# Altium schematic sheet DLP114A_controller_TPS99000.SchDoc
size 558 x 431 mm; Date: Not shown in title block; ApprovedBy: Not shown in title block; CheckedBy: Not shown in title block; Author: Not shown in title block; CompanyName: Not shown in title block; Engineer: Not shown in title block; Organization: Not shown in title block; Address1: Not shown in title block; Address2: Not shown in title block; Address3: Not shown in title block; Address4: Not shown in title block; DocumentNumber: 3; Revision: Use project parameter SCH_Rev; SheetNumber: 3; SheetTotal: 7; PageSetup: Record=PageOptions¦CenterHorizontal=True¦CenterVertical=True¦PrintScale=0.69¦XCorrection=1.00¦YCorrection=1.00¦PrintKind=0¦BorderSize=5000000¦LeftOffset=0¦BottomOffset=0¦Orientation=2¦PaperLength=1000¦PaperWidth=1000¦Scale=100¦PaperSource=15¦PrintQuality=600¦MediaType=1¦DitherType=10¦PaperKind=Letter¦PrintScaleMode=1
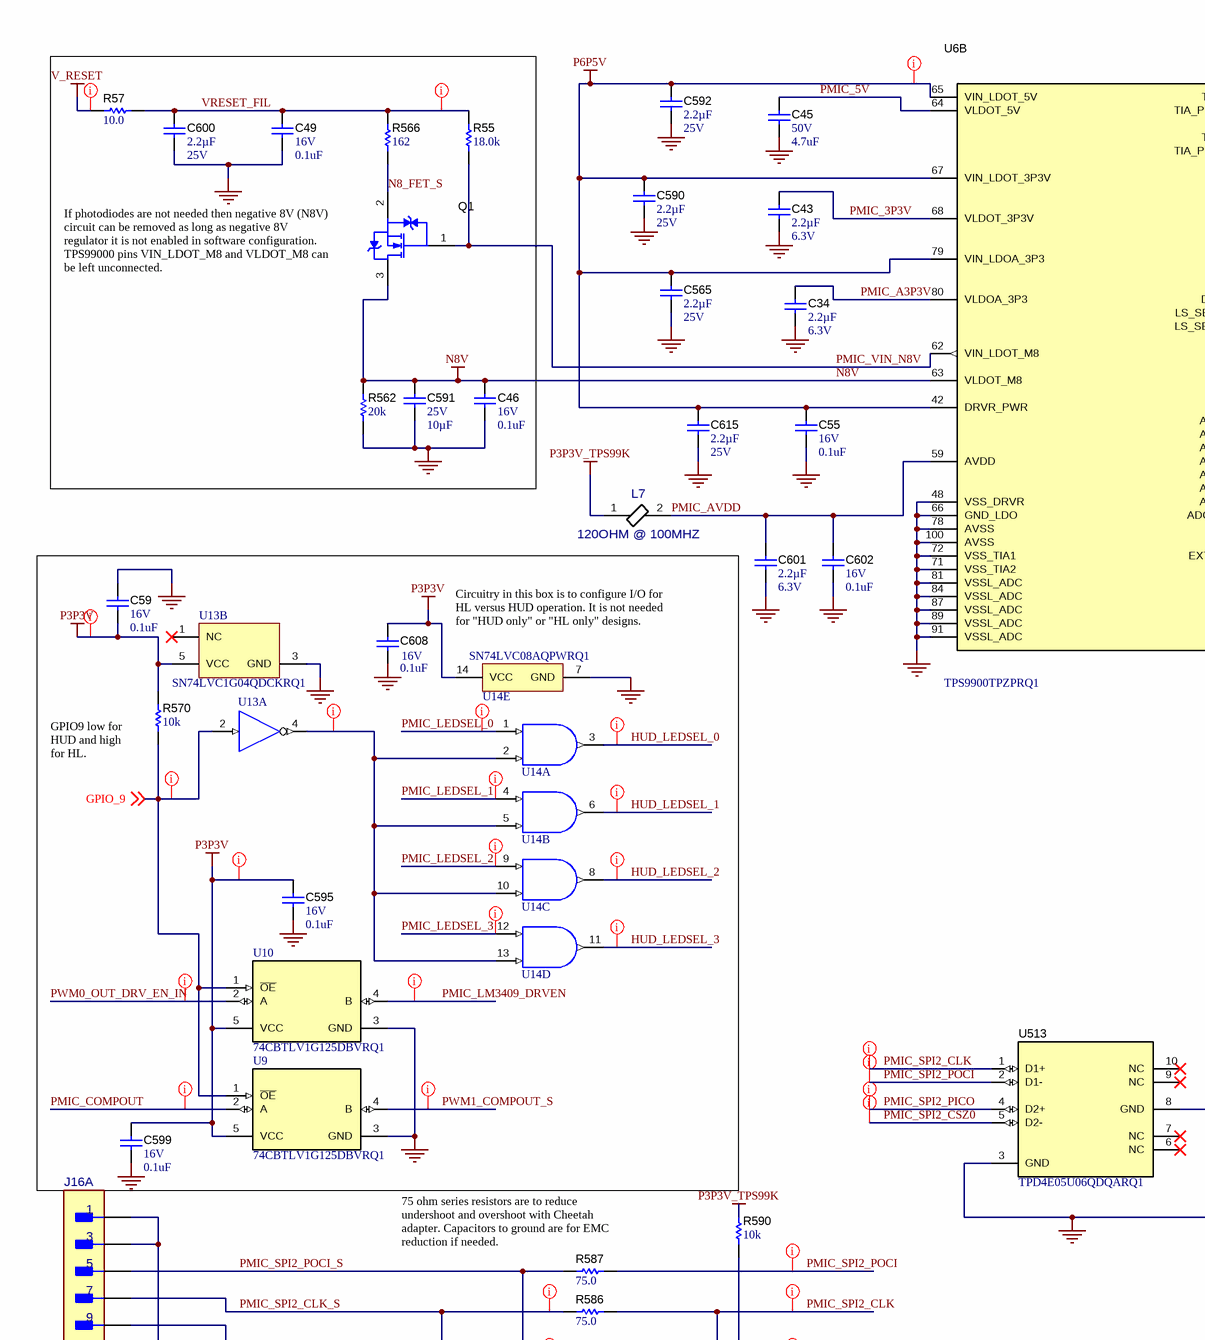
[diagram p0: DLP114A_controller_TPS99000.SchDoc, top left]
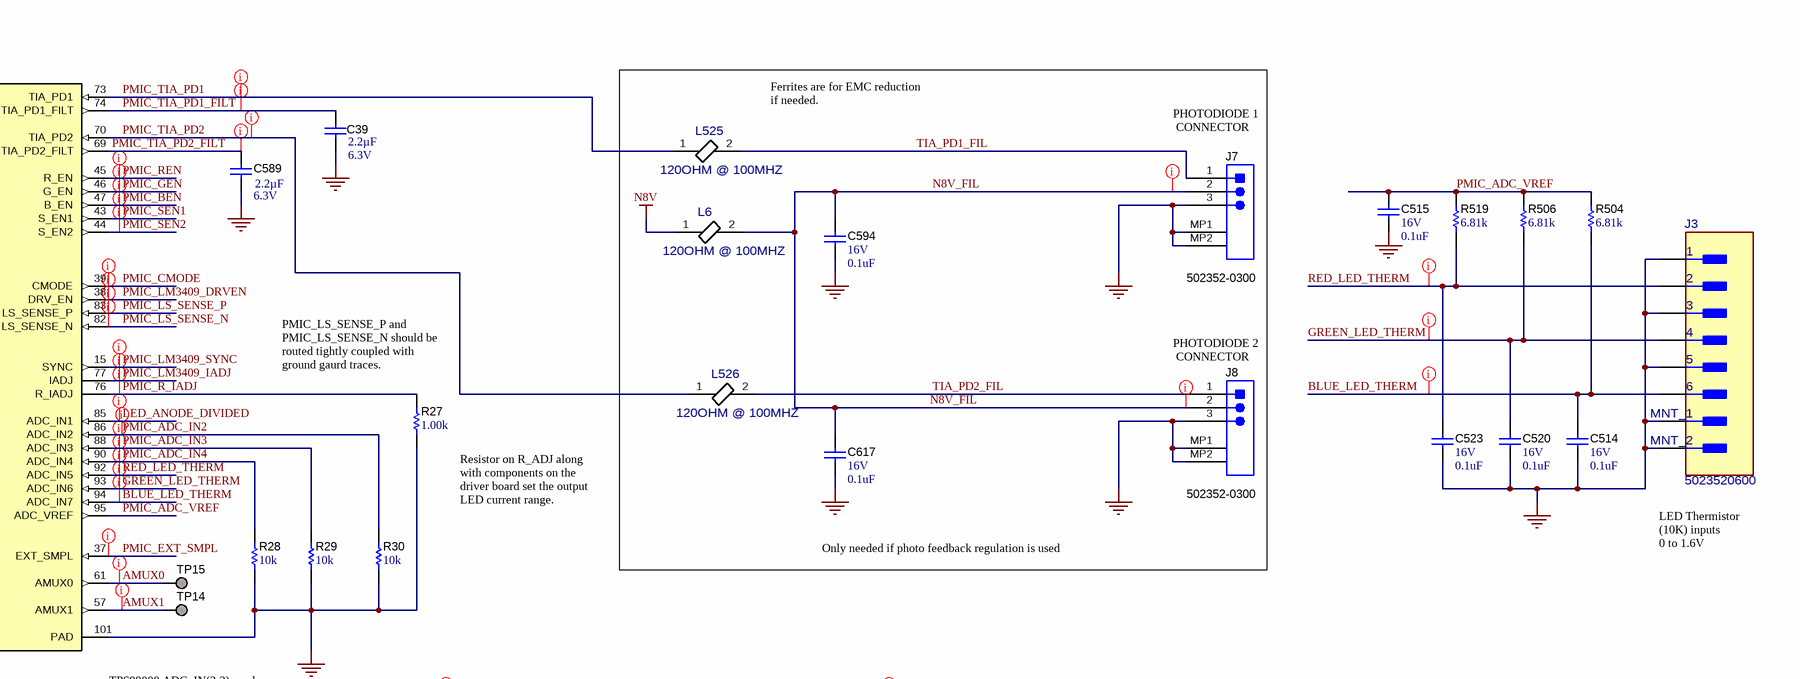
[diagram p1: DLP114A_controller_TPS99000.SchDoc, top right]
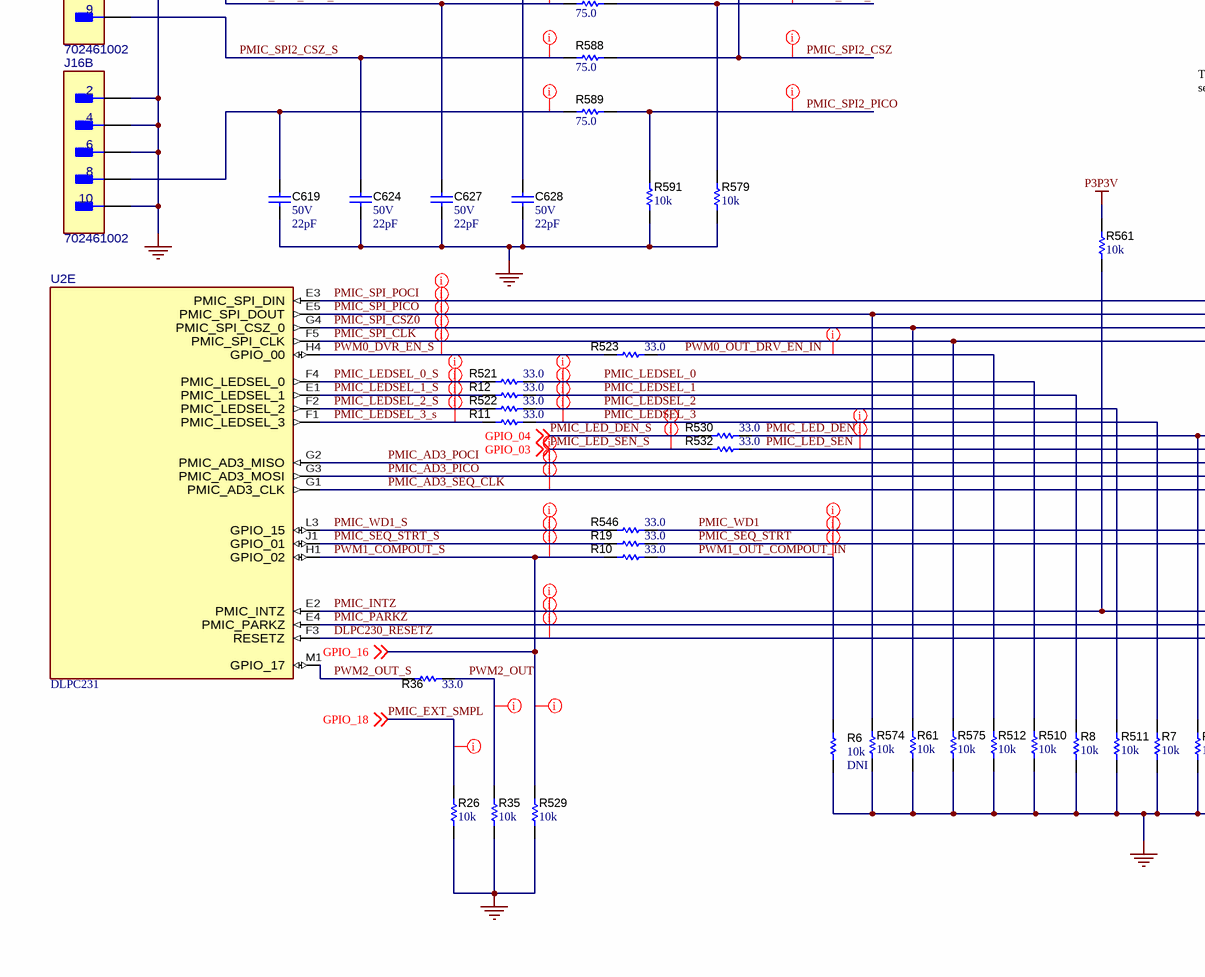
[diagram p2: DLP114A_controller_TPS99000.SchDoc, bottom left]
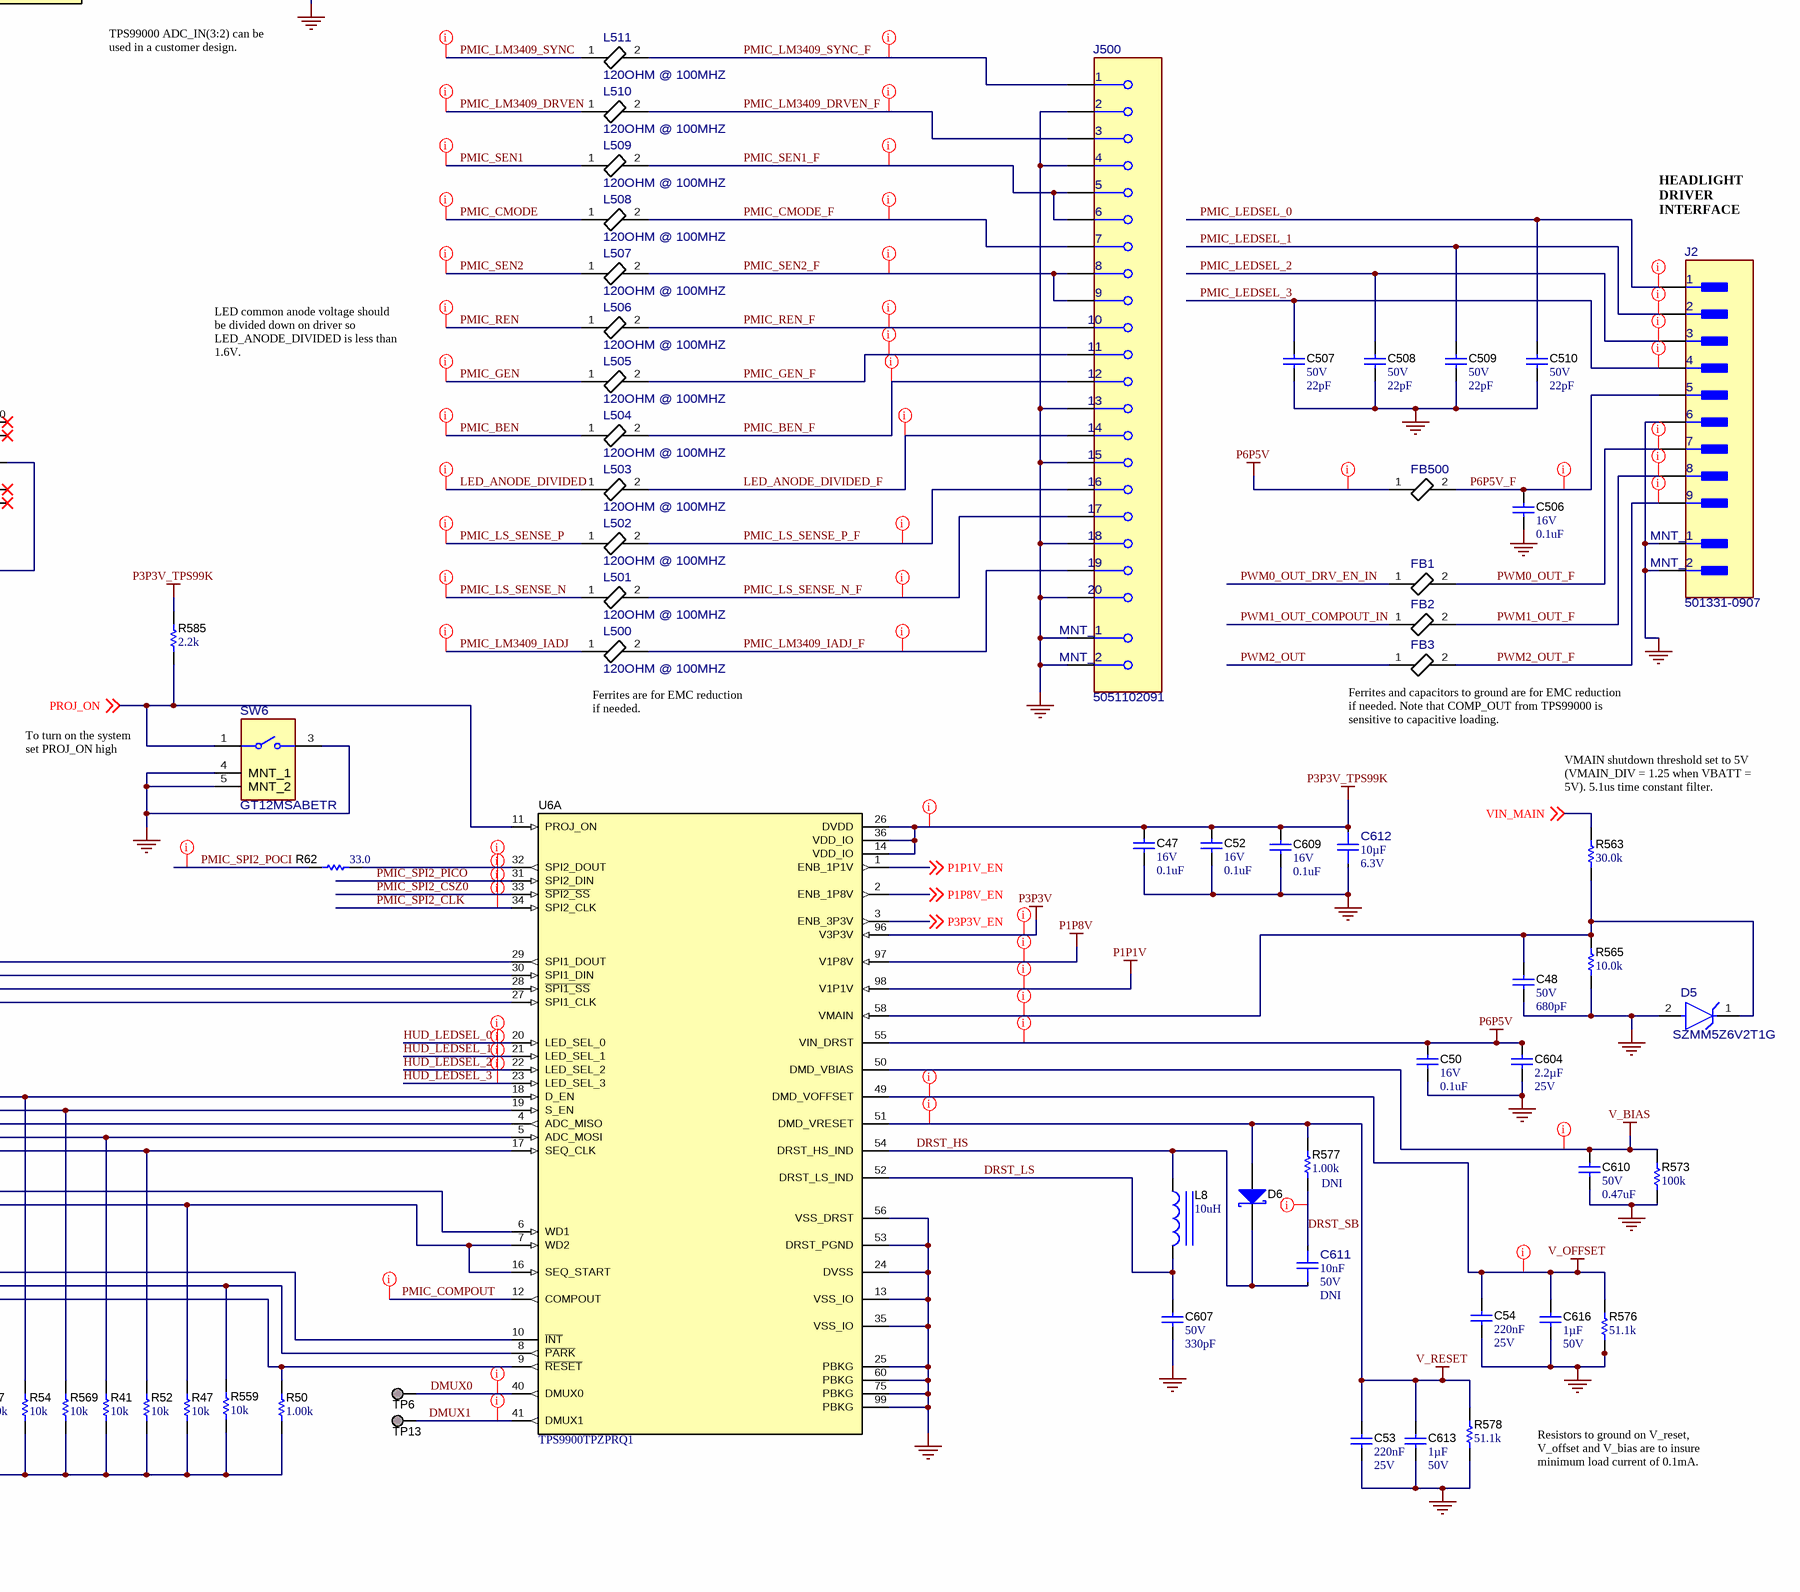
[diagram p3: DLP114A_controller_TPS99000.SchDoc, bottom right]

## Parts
C34  Cap_F: 2.2µF  VDC_V: 6.3V  [0603]  (hidden comment: GCM188R70J225KE22D)
C39  Cap_F: 2.2µF  VDC_V: 6.3V  [0603]  (hidden comment: GCM188R70J225KE22D)
C43  Cap_F: 2.2µF  VDC_V: 6.3V  [0603]  (hidden comment: GCM188R70J225KE22D)
C45  VDC_V: 50V  ValueDisplayed: 4.7uF  [1210_280]  (hidden comment: CGA6P3X7R1H475M250AB)
C46  VDC_V: 16V  ValueDisplayed: 0.1uF  [0402]  (hidden comment: GCM155R71C104KA55D)
C47  VDC_V: 16V  ValueDisplayed: 0.1uF  [0402]  (hidden comment: GCM155R71C104KA55D)
C48  VDC_V: 50V  ValueDisplayed: 680pF  [0402]  (hidden comment: GCM1555C1H681FA16D)
C49  VDC_V: 16V  ValueDisplayed: 0.1uF  [0402]  (hidden comment: GCM155R71C104KA55D)
C50  VDC_V: 16V  ValueDisplayed: 0.1uF  [0402]  (hidden comment: GCM155R71C104KA55D)
C52  VDC_V: 16V  ValueDisplayed: 0.1uF  [0402]  (hidden comment: GCM155R71C104KA55D)
C53  Cap_F: 220nF  VDC_V: 25V  [0603]  (hidden comment: GCM188R71E224KA55D)
C54  Cap_F: 220nF  VDC_V: 25V  [0603]  (hidden comment: GCM188R71E224KA55D)
C55  VDC_V: 16V  ValueDisplayed: 0.1uF  [0402]  (hidden comment: GCM155R71C104KA55D)
C59  VDC_V: 16V  ValueDisplayed: 0.1uF  [0402]  (hidden comment: GCM155R71C104KA55D)
C506  VDC_V: 16V  ValueDisplayed: 0.1uF  [0402]  (hidden comment: GCM155R71C104KA55D)
C507  VDC_V: 50V  ValueDisplayed: 22pF  [0402]  (hidden comment: CL05C220JB5NNNC)
C508  VDC_V: 50V  ValueDisplayed: 22pF  [0402]  (hidden comment: CL05C220JB5NNNC)
C509  VDC_V: 50V  ValueDisplayed: 22pF  [0402]  (hidden comment: CL05C220JB5NNNC)
C510  VDC_V: 50V  ValueDisplayed: 22pF  [0402]  (hidden comment: CL05C220JB5NNNC)
C514  VDC_V: 16V  ValueDisplayed: 0.1uF  [0402]  (hidden comment: GCM155R71C104KA55D)
C515  VDC_V: 16V  ValueDisplayed: 0.1uF  [0402]  (hidden comment: GCM155R71C104KA55D)
C520  VDC_V: 16V  ValueDisplayed: 0.1uF  [0402]  (hidden comment: GCM155R71C104KA55D)
C523  VDC_V: 16V  ValueDisplayed: 0.1uF  [0402]  (hidden comment: GCM155R71C104KA55D)
C565  Cap_F: 2.2µF  VDC_V: 25V  [0805_HV]  (hidden comment: CGA4J3X7R1E225K125AB)
C589  Cap_F: 2.2µF  VDC_V: 6.3V  [0603]  (hidden comment: GCM188R70J225KE22D)
C590  Cap_F: 2.2µF  VDC_V: 25V  [0805_HV]  (hidden comment: CGA4J3X7R1E225K125AB)
C591  VDC_V: 25V  ValueDisplayed: 10µF  [1206_180]  (hidden comment: C1206C106J3RACAUTO)
C592  Cap_F: 2.2µF  VDC_V: 25V  [0805_HV]  (hidden comment: CGA4J3X7R1E225K125AB)
C594  VDC_V: 16V  ValueDisplayed: 0.1uF  [0402]  (hidden comment: GCM155R71C104KA55D)
C595  VDC_V: 16V  ValueDisplayed: 0.1uF  [0402]  (hidden comment: GCM155R71C104KA55D)
C599  VDC_V: 16V  ValueDisplayed: 0.1uF  [0402]  (hidden comment: GCM155R71C104KA55D)
C600  Cap_F: 2.2µF  VDC_V: 25V  [0805_HV]  (hidden comment: CGA4J3X7R1E225K125AB)
C601  Cap_F: 2.2µF  VDC_V: 6.3V  [0603]  (hidden comment: GCM188R70J225KE22D)
C602  VDC_V: 16V  ValueDisplayed: 0.1uF  [0402]  (hidden comment: GCM155R71C104KA55D)
C604  Cap_F: 2.2µF  VDC_V: 25V  [0805_HV]  (hidden comment: CGA4J3X7R1E225K125AB)
C607  VDC_V: 50V  ValueDisplayed: 330pF  [0402]  (hidden comment: CGA2B2X7R1H331K050BA)
C608  VDC_V: 16V  ValueDisplayed: 0.1uF  [0402]  (hidden comment: GCM155R71C104KA55D)
C609  VDC_V: 16V  ValueDisplayed: 0.1uF  [0402]  (hidden comment: GCM155R71C104KA55D)
C610  VDC_V: 50V  ValueDisplayed: 0.47uF  [1206_180]  (hidden comment: CGA5L2X7R1H474K160AA)
C611  ValueDisplayed: 10nF  VDC_V: 50V  Parameter 1: DNI  [FP-GCM155R71H103KA55D_0402-MFG]  (hidden comment: GCM155R71H103KA55D)
C612  Cap_F: 10µF  VDC_V: 6.3V  [FP-CGA4J1X7R0J106K125AC_0805-MFG]  (hidden comment: CGA4J1X7R0J106K125AC)
C613  Cap_F: 1µF  VDC_V: 50V  [0805_HV]  (hidden comment: 08055C105K4Z2A)
C615  Cap_F: 2.2µF  VDC_V: 25V  [0805_HV]  (hidden comment: CGA4J3X7R1E225K125AB)
C616  Cap_F: 1µF  VDC_V: 50V  [0805_HV]  (hidden comment: 08055C105K4Z2A)
C617  VDC_V: 16V  ValueDisplayed: 0.1uF  [0402]  (hidden comment: GCM155R71C104KA55D)
C619  VDC_V: 50V  ValueDisplayed: 22pF  [0402]  (hidden comment: CL05C220JB5NNNC)
C624  VDC_V: 50V  ValueDisplayed: 22pF  [0402]  (hidden comment: CL05C220JB5NNNC)
C627  VDC_V: 50V  ValueDisplayed: 22pF  [0402]  (hidden comment: CL05C220JB5NNNC)
C628  VDC_V: 50V  ValueDisplayed: 22pF  [0402]  (hidden comment: CL05C220JB5NNNC)
D5  SZMM5Z6V2T1G  [FP-SZMM5Z6V2T1G_SOD523-MFG]
D6  MBR0540T1G  [SOD-123]  (value not drawn)
FB1  MMZ1005Y121CTD25  [FP-MMZ1005Y121CTD25_0402-MFG]  (value not drawn)
FB2  MMZ1005Y121CTD25  [FP-MMZ1005Y121CTD25_0402-MFG]  (value not drawn)
FB3  MMZ1005Y121CTD25  [FP-MMZ1005Y121CTD25_0402-MFG]  (value not drawn)
FB500  MMZ1005Y121CTD25  [FP-MMZ1005Y121CTD25_0402-MFG]  (value not drawn)
J2  501331-0907  [FP-501331-0907_HDR9-MFG]
J3  5023520600  [FP-5023520600_HDR6-MFG]
J7  502352-0300  [Molex_502352-0300]
J8  502352-0300  [Molex_502352-0300]
J16  702461002  [FP-702461002_HDR10-MFG]  (parts A,B of 2)
J500  5051102091  [FP-5051102091_CONN_FFC_FPC20-MFG]
L6  120OHM @ 100MHZ  [FP-MMZ1005Y121CTD25_0402-MFG]
L7  120OHM @ 100MHZ  [FP-MMZ1005Y121CTD25_0402-MFG]
L8  ValueDisplayed: 10uH  [CDRH5D18]  (hidden comment: CDRH5D18NP-100NC)
L500  120OHM @ 100MHZ  [FP-MMZ1005Y121CTD25_0402-MFG]
L501  120OHM @ 100MHZ  [FP-MMZ1005Y121CTD25_0402-MFG]
L502  120OHM @ 100MHZ  [FP-MMZ1005Y121CTD25_0402-MFG]
L503  120OHM @ 100MHZ  [FP-MMZ1005Y121CTD25_0402-MFG]
L504  120OHM @ 100MHZ  [FP-MMZ1005Y121CTD25_0402-MFG]
L505  120OHM @ 100MHZ  [FP-MMZ1005Y121CTD25_0402-MFG]
L506  120OHM @ 100MHZ  [FP-MMZ1005Y121CTD25_0402-MFG]
L507  120OHM @ 100MHZ  [FP-MMZ1005Y121CTD25_0402-MFG]
L508  120OHM @ 100MHZ  [FP-MMZ1005Y121CTD25_0402-MFG]
L509  120OHM @ 100MHZ  [FP-MMZ1005Y121CTD25_0402-MFG]
L510  120OHM @ 100MHZ  [FP-MMZ1005Y121CTD25_0402-MFG]
L511  120OHM @ 100MHZ  [FP-MMZ1005Y121CTD25_0402-MFG]
L525  120OHM @ 100MHZ  [FP-MMZ1005Y121CTD25_0402-MFG]
L526  120OHM @ 100MHZ  [FP-MMZ1005Y121CTD25_0402-MFG]
Q1  NX3008NBKW,115  [SOT-323]  (value not drawn)
R6  ValueDisplayed: 10k  Parameter 1: DNI  [0402]  (hidden comment: ERJ-2GEJ103X)
R7  ValueDisplayed: 10k  [0402]  (hidden comment: ERJ-2GEJ103X)
R8  ValueDisplayed: 10k  [0402]  (hidden comment: ERJ-2GEJ103X)
R10  ValueDisplayed: 33.0  [0402]  (hidden comment: ERJ-2RKF33R0X)
R11  ValueDisplayed: 33.0  [0402]  (hidden comment: ERJ-2RKF33R0X)
R12  ValueDisplayed: 33.0  [0402]  (hidden comment: ERJ-2RKF33R0X)
R19  ValueDisplayed: 33.0  [0402]  (hidden comment: ERJ-2RKF33R0X)
R26  ValueDisplayed: 10k  [0402]  (hidden comment: ERJ-2GEJ103X)
R27  ValueDisplayed: 1.00k  [0402]  (hidden comment: CRCW04021K00FKED)
R28  ValueDisplayed: 10k  [0402]  (hidden comment: ERJ-2GEJ103X)
R29  ValueDisplayed: 10k  [0402]  (hidden comment: ERJ-2GEJ103X)
R30  ValueDisplayed: 10k  [0402]  (hidden comment: ERJ-2GEJ103X)
R35  ValueDisplayed: 10k  [0402]  (hidden comment: ERJ-2GEJ103X)
R36  ValueDisplayed: 33.0  [0402]  (hidden comment: ERJ-2RKF33R0X)
R41  ValueDisplayed: 10k  [0402]  (hidden comment: ERJ-2GEJ103X)
R47  ValueDisplayed: 10k  [0402]  (hidden comment: ERJ-2GEJ103X)
R50  ValueDisplayed: 1.00k  [0402]  (hidden comment: CRCW04021K00FKED)
R52  ValueDisplayed: 10k  [0402]  (hidden comment: ERJ-2GEJ103X)
R54  ValueDisplayed: 10k  [0402]  (hidden comment: ERJ-2GEJ103X)
R55  ValueDisplayed: 18.0k  [0402]  (hidden comment: ERJ2RKF1802X)
R57  ValueDisplayed: 10.0  [0402]  (hidden comment: CRCW040210R0FKED)
R61  ValueDisplayed: 10k  [0402]  (hidden comment: ERJ-2GEJ103X)
R62  ValueDisplayed: 33.0  [0402]  (hidden comment: ERJ-2RKF33R0X)
R504  ValueDisplayed: 6.81k  [0402]  (hidden comment: CRCW04026K81FKED)
R506  ValueDisplayed: 6.81k  [0402]  (hidden comment: CRCW04026K81FKED)
R510  ValueDisplayed: 10k  [0402]  (hidden comment: ERJ-2GEJ103X)
R511  ValueDisplayed: 10k  [0402]  (hidden comment: ERJ-2GEJ103X)
R512  ValueDisplayed: 10k  [0402]  (hidden comment: ERJ-2GEJ103X)
R519  ValueDisplayed: 6.81k  [0402]  (hidden comment: CRCW04026K81FKED)
R521  ValueDisplayed: 33.0  [0402]  (hidden comment: ERJ-2RKF33R0X)
R522  ValueDisplayed: 33.0  [0402]  (hidden comment: ERJ-2RKF33R0X)
R523  ValueDisplayed: 33.0  [0402]  (hidden comment: ERJ-2RKF33R0X)
R529  ValueDisplayed: 10k  [0402]  (hidden comment: ERJ-2GEJ103X)
R530  ValueDisplayed: 33.0  [0402]  (hidden comment: ERJ-2RKF33R0X)
R532  ValueDisplayed: 33.0  [0402]  (hidden comment: ERJ-2RKF33R0X)
R546  ValueDisplayed: 33.0  [0402]  (hidden comment: ERJ-2RKF33R0X)
R559  ValueDisplayed: 10k  [0402]  (hidden comment: ERJ-2GEJ103X)
R561  ValueDisplayed: 10k  [0402]  (hidden comment: ERJ-2GEJ103X)
R562  ValueDisplayed: 20k  [0402]  (hidden comment: ERJ-2GEJ203X)
R563  ValueDisplayed: 30.0k  [0402]  (hidden comment: CRCW040230K0FKED)
R565  ValueDisplayed: 10.0k  [0402]  (hidden comment: ERJ-2RKF1002X)
R566  ValueDisplayed: 162  [0402]  (hidden comment: CRCW0402162RFKED)
R569  ValueDisplayed: 10k  [0402]  (hidden comment: ERJ-2GEJ103X)
R570  ValueDisplayed: 10k  [0402]  (hidden comment: ERJ-2GEJ103X)
R573  ValueDisplayed: 100k  [0402]  (hidden comment: ERJ-2GEJ104X)
R574  ValueDisplayed: 10k  [0402]  (hidden comment: ERJ-2GEJ103X)
R575  ValueDisplayed: 10k  [0402]  (hidden comment: ERJ-2GEJ103X)
R576  ValueDisplayed: 51.1k  [0402]  (hidden comment: CRCW040251K1FKED)
R577  ValueDisplayed: 1.00k  Parameter 1: DNI  [0402]  (hidden comment: CRCW04021K00FKED)
R578  ValueDisplayed: 51.1k  [0402]  (hidden comment: CRCW040251K1FKED)
R579  ValueDisplayed: 10k  [0402]  (hidden comment: ERJ-2GEJ103X)
R585  ValueDisplayed: 2.2k  [0402]  (hidden comment: CRCW04022K20JNED)
R586  ValueDisplayed: 75.0  [0402]  (hidden comment: CRCW040275R0FKED)
R587  ValueDisplayed: 75.0  [0402]  (hidden comment: CRCW040275R0FKED)
R588  ValueDisplayed: 75.0  [0402]  (hidden comment: CRCW040275R0FKED)
R589  ValueDisplayed: 75.0  [0402]  (hidden comment: CRCW040275R0FKED)
R590  ValueDisplayed: 10k  [0402]  (hidden comment: ERJ-2GEJ103X)
R591  ValueDisplayed: 10k  [0402]  (hidden comment: ERJ-2GEJ103X)
SW6  GT12MSABETR  [FP-GT12MSABETR_SMT_7MM01_6MM93-MFG]
TP6  TESTPOINT  [TESTPOINT]  (value not drawn)  (no BOM)
TP13  TESTPOINT  [TESTPOINT]  (value not drawn)  (no BOM)
TP14  TESTPOINT  [TESTPOINT]  (value not drawn)  (no BOM)
TP15  TESTPOINT  [TESTPOINT]  (value not drawn)  (no BOM)
U2  DLPC231  [ZEK0324A-MFG]  (part E of 9)
U6  TPS9900TPZPRQ1  [PZP0100K]  (parts A,B of 2)
U9  74CBTLV1G125DBVRQ1  [DBV0005A_N]
U10  74CBTLV1G125DBVRQ1  [DBV0005A_N]
U13  SN74LVC1G04QDCKRQ1  [DCK0005A_N]  (value not drawn)  (parts A,B of 2)
U14  SN74LVC08AQPWRQ1  [PW0014A_N]  (parts A,B,C,D,E of 5)
U513  TPD4E05U06QDQARQ1  [DQA0010A]

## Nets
GND: C34.2 C39.2 C43.2 C45.2 C46.2 C47.2 C48.2 C49.2 C50.2 C52.2 C53.2 C54.2 C55.2 C59.2 C506.2 C507.2 C508.2 C509.2 C510.2 C514.2 C515.2 C520.2 C523.2 C565.2 C589.2 C590.2 C591.2 C592.2 C594.2 C595.2 C599.2 C600.2 C601.2 C602.2 C604.2 C607.2 C608.2 C609.2 C610.2 C612.1 C613.2 C615.2 C616.2 C617.2 C619.2 C624.2 C627.2 C628.2 D5.2(ANODE) J2.6 J2.10(MNT_1) J2.11(MNT_2) J3.1 J3.3 J3.5 J3.7(MNT_1) J3.8(MNT_2) J7.3 J7.MP1 J7.MP2 J8.3 J8.MP1 J8.MP2 J16.1 J16.2 J16.3 J16.4 J16.6 J16.10 J500.2 J500.4 J500.13 J500.15 J500.18 J500.20 J500.21(MNT_1) J500.22(MNT_2) R6.1 R7.1 R8.1 R26.1 R27.1 R28.1 R29.1 R30.1 R35.1 R41.1 R47.1 R50.1 R52.1 R54.1 R61.1 R510.1 R511.1 R512.1 R529.1 R559.1 R562.1 R565.1 R569.1 R573.1 R574.1 R575.1 R576.1 R578.1 R579.1 R591.1 SW6.3 SW6.4(MNT_1) SW6.5(MNT_2) U6.13(VSS_IO) U6.24(DVSS) U6.25(PBKG) U6.35(VSS_IO) U6.48(VSS_DRVR) U6.53(DRST_PGND) U6.56(VSS_DRST) U6.60(PBKG) U6.66(GND_LDO) U6.71(VSS_TIA2) U6.72(VSS_TIA1) U6.75(PBKG) U6.78(AVSS) U6.81(VSSL_ADC) U6.84(VSSL_ADC) U6.87(VSSL_ADC) U6.89(VSSL_ADC) U6.91(VSSL_ADC) U6.99(PBKG) U6.100(AVSS) U6.101(PAD) U9.3(GND) U10.3(GND) U13.3(GND) U14.7(GND) U513.3(GND) U513.8(GND)
N8V: C46.1 C591.1 L6.1 Q1.3(D) R562.2 U6.63(VLDOT_M8)
P1P1V: U6.98(V1P1V)
P1P8V: U6.97(V1P8V)
P3P3V: C59.1 C595.1 C599.1 C608.1 R561.2 R570.2 U6.96(V3P3V) U9.5(VCC) U10.5(VCC) U13.5(VCC) U14.14(VCC)
P3P3V_TPS99K: C47.1 C52.1 C609.1 C612.2 L7.1 R585.2 R590.2 U6.14(VDD_IO) U6.26(DVDD) U6.36(VDD_IO)
P6P5V: C50.1 C55.1 C565.1 C590.1 C592.1 C604.1 C615.1 FB500.1 U6.42(DRVR_PWR) U6.55(VIN_DRST) U6.65(VIN_LDOT_5V) U6.67(VIN_LDOT_3P3V) U6.79(VIN_LDOA_3P3)
V_BIAS: C610.1 R573.2 U6.50(DMD_VBIAS)
V_OFFSET: C54.1 C616.1 R576.2 U6.49(DMD_VOFFSET)
V_RESET: C53.1 C613.1 D6.2(A) R57.1 R577.2 R578.2 U6.51(DMD_VRESET)
AMUX0: TP15.1 U6.61(AMUX0)
AMUX1: TP14.1 U6.57(AMUX1)
BLUE_LED_THERM: C514.1 J3.6 R504.1 U6.94(ADC_IN7)
DLPC230_RESETZ: R50.2 U2.F3(RESETZ) U6.9(~{RESET})
DMUX0: TP6.1 U6.40(DMUX0)
DMUX1: TP13.1 U6.41(DMUX1)
DRST_HS: C611.1 D6.1(K) L8.1 U6.54(DRST_HS_IND)
DRST_LS: C607.1 L8.2 U6.52(DRST_LS_IND)
DRST_SB: C611.2 R577.1
GPIO_9: R570.1 U9.1(~{OE}) U10.1(~{OE}) U13.2(A) ; off-sheet GPIO_9
GREEN_LED_THERM: C520.1 J3.4 R506.1 U6.93(ADC_IN6)
HUD_LEDSEL_0: U6.20(LED_SEL_0) U14.3(1Y)
HUD_LEDSEL_1: U6.21(LED_SEL_1) U14.6(2Y)
HUD_LEDSEL_2: U6.22(LED_SEL_2) U14.8(3Y)
HUD_LEDSEL_3: U6.23(LED_SEL_3) U14.11(4Y)
LED_ANODE_DIVIDED: L503.1 U6.85(ADC_IN1)
LED_ANODE_DIVIDED_F: J500.14 L503.2
N8_FET_S: Q1.2(S) R566.1
N8V_FIL: C594.1 C617.1 J7.2 J8.2 L6.2
P1P1V_EN: U6.1(ENB_1P1V) ; off-sheet P1P1V_EN
P1P8V_EN: U6.2(ENB_1P8V) ; off-sheet P1P8V_EN
P3P3V_EN: U6.3(ENB_3P3V) ; off-sheet P3P3V_EN
P6P5V_F: C506.1 FB500.2 J2.5
PMIC_3P3V: C43.1 U6.68(VLDOT_3P3V)
PMIC_5V: C45.1 U6.64(VLDOT_5V)
PMIC_A3P3V: C34.1 U6.80(VLDOA_3P3)
PMIC_AD3_PICO: R41.2 U2.G3(PMIC_AD3_MOSI) U6.5(ADC_MOSI)
PMIC_AD3_POCI: U2.G2(PMIC_AD3_MISO) U6.4(ADC_MISO)
PMIC_AD3_SEQ_CLK: R52.2 U2.G1(PMIC_AD3_CLK) U6.17(SEQ_CLK)
PMIC_ADC_IN2: R30.2 U6.86(ADC_IN2)
PMIC_ADC_IN3: R29.2 U6.88(ADC_IN3)
PMIC_ADC_IN4: R28.2 U6.90(ADC_IN4)
PMIC_ADC_VREF: C515.1 R504.2 R506.2 R519.2 U6.95(ADC_VREF)
PMIC_AVDD: C601.1 C602.1 L7.2 U6.59(AVDD)
PMIC_BEN: L504.1 U6.47(B_EN)
PMIC_BEN_F: J500.12 L504.2
PMIC_CMODE: L508.1 U6.39(CMODE)
PMIC_CMODE_F: J500.7 L508.2
PMIC_COMPOUT: U6.12(COMPOUT) U9.2(A)
PMIC_EXT_SMPL: R26.2 U6.37(EXT_SMPL) ; off-sheet GPIO_18  [also labelled GPIO_18]
PMIC_GEN: L505.1 U6.46(G_EN)
PMIC_GEN_F: J500.11 L505.2
PMIC_INTZ: R561.1 U2.E2(PMIC_INTZ) U6.10(~{INT})
PMIC_LED_DEN: R54.2 R530.2 U6.18(D_EN)
PMIC_LED_DEN_S: R530.1 ; off-sheet GPIO_04  [also labelled GPIO_04]
PMIC_LED_SEN: R532.2 R569.2 U6.19(S_EN)
PMIC_LED_SEN_S: R532.1 ; off-sheet GPIO_03  [also labelled GPIO_03]
PMIC_LEDSEL_0: C510.1 J2.1 R510.2 R521.2 U14.1(1A)
PMIC_LEDSEL_0_S: R521.1 U2.F4(PMIC_LEDSEL_0)
PMIC_LEDSEL_1: C509.1 J2.2 R8.2 R12.2 U14.4(2A)
PMIC_LEDSEL_1_S: R12.1 U2.E1(PMIC_LEDSEL_1)
PMIC_LEDSEL_2: C508.1 J2.3 R511.2 R522.2 U14.9(3A)
PMIC_LEDSEL_2_S: R522.1 U2.F2(PMIC_LEDSEL_2)
PMIC_LEDSEL_3: C507.1 J2.4 R7.2 R11.2 U14.12(4A)
PMIC_LEDSEL_3_s: R11.1 U2.F1(PMIC_LEDSEL_3)
PMIC_LM3409_DRVEN: L510.1 U6.38(DRV_EN) U10.4(B)
PMIC_LM3409_DRVEN_F: J500.3 L510.2
PMIC_LM3409_IADJ: L500.1 U6.77(IADJ)
PMIC_LM3409_IADJ_F: J500.19 L500.2
PMIC_LM3409_SYNC: L511.1 U6.15(SYNC)
PMIC_LM3409_SYNC_F: J500.1 L511.2
PMIC_LS_SENSE_N: L501.1 U6.82(LS_SENSE_N)
PMIC_LS_SENSE_N_F: J500.17 L501.2
PMIC_LS_SENSE_P: L502.1 U6.83(LS_SENSE_P)
PMIC_LS_SENSE_P_F: J500.16 L502.2
PMIC_PARKZ: R559.2 U2.E4(PMIC_PARKZ) U6.8(~{PARK})
PMIC_R_IADJ: R27.2 U6.76(R_IADJ)
PMIC_REN: L506.1 U6.45(R_EN)
PMIC_REN_F: J500.10 L506.2
PMIC_SEN1: L509.1 U6.43(S_EN1)
PMIC_SEN1_F: J500.5 J500.6 L509.2
PMIC_SEN2: L507.1 U6.44(S_EN2)
PMIC_SEN2_F: J500.8 J500.9 L507.2
PMIC_SEQ_STRT: R19.2 R47.2 U6.7(WD2) U6.16(SEQ_START)
PMIC_SEQ_STRT_S: R19.1 U2.J1(GPIO_01)
PMIC_SPI2_CLK: R579.2 R586.2 U6.34(SPI2_CLK) U513.1(D1+)
PMIC_SPI2_CLK_S: C627.1 J16.7 R586.1
PMIC_SPI2_CSZ: R588.2 R590.1
PMIC_SPI2_CSZ0: U6.33(~{SPI2_SS}) U513.5(D2-)
PMIC_SPI2_CSZ_S: C624.1 J16.9 R588.1
PMIC_SPI2_PICO: R589.2 R591.2 U6.31(SPI2_DIN) U513.4(D2+)
PMIC_SPI2_POCI: R62.1 R587.2 U513.2(D1-)
PMIC_SPI2_POCI_S: C628.1 J16.5 R587.1
PMIC_SPI_CLK: R575.2 U2.F5(PMIC_SPI_CLK) U6.27(SPI1_CLK)
PMIC_SPI_CSZ0: R61.2 U2.G4(PMIC_SPI_CSZ_0) U6.28(~{SPI1_SS})
PMIC_SPI_PICO: R574.2 U2.E5(PMIC_SPI_DOUT) U6.30(SPI1_DIN)
PMIC_SPI_POCI: U2.E3(PMIC_SPI_DIN) U6.29(SPI1_DOUT)
PMIC_TIA_PD1: L525.1 U6.73(TIA_PD1)
PMIC_TIA_PD1_FILT: C39.1 U6.74(TIA_PD1_FILT)
PMIC_TIA_PD2: L526.1 U6.70(TIA_PD2)
PMIC_TIA_PD2_FILT: C589.1 U6.69(TIA_PD2_FILT)
PMIC_VIN_N8V: Q1.1(G) R55.1 U6.62(VIN_LDOT_M8)
PMIC_WD1: R546.2 U6.6(WD1)
PMIC_WD1_S: R546.1 U2.L3(GPIO_15)
PROJ_ON: R585.1 SW6.1 U6.11(PROJ_ON) ; off-sheet PROJ_ON
PWM0_DVR_EN_S: R523.1 U2.H4(GPIO_00)
PWM0_OUT_DRV_EN_IN: FB1.1 R512.2 R523.2 U10.2(A)
PWM0_OUT_F: FB1.2 J2.7
PWM1_COMPOUT_S: R10.1 R529.2 U2.H1(GPIO_02) U9.4(B) ; off-sheet GPIO_16  [also labelled GPIO_16]
PWM1_OUT_COMPOUT_IN: FB2.1 R6.2 R10.2
PWM1_OUT_F: FB2.2 J2.8
PWM2_OUT: FB3.1 R35.2 R36.2
PWM2_OUT_F: FB3.2 J2.9
PWM2_OUT_S: R36.1 U2.M1(GPIO_17)
RED_LED_THERM: C523.1 J3.2 R519.1 U6.92(ADC_IN5)
TIA_PD1_FIL: J7.1 L525.2
TIA_PD2_FIL: J8.1 L526.2
VIN_MAIN: R563.2 ; off-sheet VIN_MAIN
VRESET_FIL: C49.1 C600.1 R55.2 R57.2 R566.2
NetC48_1: C48.1 D5.1(CATHODE) R563.1 R565.2 U6.58(VMAIN)
NetC619_1: C619.1 J16.8 R589.1
NetR62_2: R62.2 U6.32(SPI2_DOUT)
NetU13_4: U13.4(Y) U14.2(1B) U14.5(2B) U14.10(3B) U14.13(4B)

Not connected (* = marked no-connect by the designer): U13 1(NC)*; U513 6(NC)* 7(NC)* 9(NC)* 10(NC)*

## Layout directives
net class 50OHM: AMUX0, AMUX1, BLUE_LED_THERM, DLPC230_RESETZ, DMUX0, DMUX1, DRST_SB, GPIO_9, GREEN_LED_THERM, HUD_LEDSEL_0, HUD_LEDSEL_1, HUD_LEDSEL_2, HUD_LEDSEL_3, LED_ANODE_DIVIDED, LED_ANODE_DIVIDED_F, N8V_FIL, NetC619_1, NetR62_2, NetU13_4, PMIC_AD3_PICO, PMIC_AD3_POCI, PMIC_AD3_SEQ_CLK, PMIC_ADC_IN2, PMIC_ADC_IN3, PMIC_ADC_IN4, PMIC_BEN, PMIC_BEN_F, PMIC_CMODE, PMIC_CMODE_F, PMIC_COMPOUT, PMIC_EXT_SMPL, PMIC_GEN, PMIC_GEN_F, PMIC_INTZ, PMIC_LED_DEN, PMIC_LED_DEN_S, PMIC_LED_SEN, PMIC_LED_SEN_S, PMIC_LEDSEL_0, PMIC_LEDSEL_0_S, PMIC_LEDSEL_1, PMIC_LEDSEL_1_S, PMIC_LEDSEL_2, PMIC_LEDSEL_2_S, PMIC_LEDSEL_3, PMIC_LEDSEL_3_s, PMIC_LM3409_DRVEN, PMIC_LM3409_DRVEN_F, PMIC_LM3409_IADJ, PMIC_LM3409_IADJ_F, PMIC_LM3409_SYNC, PMIC_LM3409_SYNC_F, PMIC_LS_SENSE_N, PMIC_LS_SENSE_N_F, PMIC_LS_SENSE_P, PMIC_LS_SENSE_P_F, PMIC_PARKZ, PMIC_R_IADJ, PMIC_REN, PMIC_REN_F, PMIC_SEN1, PMIC_SEN1_F, PMIC_SEN2, PMIC_SEN2_F, PMIC_SEQ_STRT, PMIC_SEQ_STRT_S, PMIC_SPI2_CLK, PMIC_SPI2_CLK_S, PMIC_SPI2_CSZ, PMIC_SPI2_CSZ0, PMIC_SPI2_CSZ_S, PMIC_SPI2_PICO, PMIC_SPI2_POCI, PMIC_SPI_CLK, PMIC_SPI_CSZ0, PMIC_SPI_PICO, PMIC_SPI_POCI, PMIC_TIA_PD1, PMIC_TIA_PD1_FILT, PMIC_TIA_PD2, PMIC_TIA_PD2_FILT, PMIC_WD1, PMIC_WD1_S, PWM0_DVR_EN_S, PWM0_OUT_DRV_EN_IN, PWM0_OUT_F, PWM1_COMPOUT_S, PWM1_OUT_COMPOUT_IN, PWM1_OUT_F, PWM2_OUT, PWM2_OUT_F, RED_LED_THERM, VRESET_FIL
net class POWER: NetC48_1, P1P1V, P1P8V, P3P3V, P3P3V_TPS99K, P6P5V, P6P5V_F
net class Voltage Spacing (15Mils): V_BIAS, V_OFFSET, V_RESET

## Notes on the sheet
- Ferrites are for EMC reduction
  if needed.
- (near J7) PHOTODIODE 1
  CONNECTOR
- (near Q1) If photodiodes are not needed then negative 8V (N8V)
  circuit can be removed as long as negative 8V
  regulator it is not enabled in software configuration.
  TPS99000 pins VIN_LDOT_M8 and VLDOT_M8 can
  be left unconnected.
- (near R27) PMIC_LS_SENSE_P and
  PMIC_LS_SENSE_N should be
  routed tightly coupled with
  ground gaurd traces.
- (near J8) PHOTODIODE 2
  CONNECTOR
- (near R27) Resistor on R_ADJ along
  with components on the
  driver board set the output
  LED current range.
- Only needed if photo feedback regulation is used
- LED Thermistor
  (10K) inputs
  0 to 1.6V
- (near U14) Circuitry in this box is to configure I/O for HL versus HUD operation. It is not needed for "HUD only" or "HL only" designs.
- TPS99000 ADC_IN(3:2) can be
  used in a customer design.
- (near R570) GPIO9 low for HUD and high for HL.
- HEADLIGHT
  DRIVER
  INTERFACE
- LED common anode voltage should
  be divided down on driver so
  LED_ANODE_DIVIDED is less than
  1.6V.
- (near R587) 75 ohm series resistors are to reduce
  undershoot and overshoot with Cheetah
  adapter. Capacitors to ground are for EMC
  reduction if needed.
- (near L500) Ferrites are for EMC reduction
  if needed.
- (near FB3) Ferrites and capacitors to ground are for EMC reduction
  if needed. Note that COMP_OUT from TPS99000 is
  sensitive to capacitive loading.
- To turn on the system
  set PROJ_ON high
- (near R563) VMAIN shutdown threshold set to 5V
  (VMAIN_DIV = 1.25 when VBATT =
  5V). 5.1us time constant filter.
- Resistors to ground on V_reset,
  V_offset and V_bias are to insure
  minimum load current of 0.1mA.

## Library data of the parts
C34 C39 C43 C589 C601 = CMP-0007134-5: CAP, CERM, 2.2 uF, 6.3 V, +/- 10%, X7R, AEC-Q200 Grade 1, 0603; Manufacturer: MuRata; TaMin_C: -55°C; Polarized: N; SizeAreaWB_mm2: 4.68; Value1: Unknown; U/M: EA; Value: 2.2uF; TaMax_C: 125°C; SizeZ_mm: 1; SizeX_mm: 1.6; SizeY_mm: 0.8; SizeArea_mm2: 1.28; AEC Qualified: Y; AEC Category: Q200
C45 = CMP-0009163-2: CAP, CERM, 4.7 uF, 50 V, +/- 20%, X7R, AEC-Q200 Grade 1, 1210; Manufacturer: TDK; TaMin_C: -55°C; Polarized: N; SizeAreaWB_mm2: 14.7; Value1: Unknown; U/M: EA; Value: 4.7uF; TaMax_C: 125°C; SizeZ_mm: 2.8; SizeX_mm: 3.2; SizeY_mm: 2.5; Cap_Case: 1210; SizeArea_mm2: 8; AEC Qualified: Y; Cap_F: 4.7µF; AEC Grade: 1; AEC Category: Q200
C46 C47 C49 C50 C52 C55 C59 C506 C514 C515 C520 C523 C594 C595 C599 C602 C608 C609 C617 = CMP-0006351-2: CAP, CERM, 0.1 uF, 16 V, +/- 10%, X7R, 0402; Manufacturer: MuRata; TaMin_C: -55°C; Polarized: N; SizeAreaWB_mm2: 3; Value1: Unknown; U/M: EA; Value: 0.1uF; TaMax_C: 125°C; SizeZ_mm: 0.6; SizeX_mm: 1; SizeY_mm: 0.5; Cap_F: 100nF; AEC Category: Q200
C48 = CMP-0086096-1: CAP, CERM, 680 pF, 50 V,+/- 1%, C0G/NP0, AEC-Q200 Grade 1, 0402; Manufacturer: MuRata; SizeArea_mm2: 0.5; Polarized: N; SizeZ_mm: 0.6; SizeAreaWB_mm2: 3; AEC Qualified: Y; Value: 680pF; TaMin_C: -55°C; SizeX_mm: 1; U/M: EA; TaMax_C: 125°C; AEC Category: Q200
C53 C54 = CMP-0007140-4: CAP, CERM, 0.22 uF, 25 V, +/- 10%, X7R, AEC-Q200 Grade 1, 0603; Manufacturer: MuRata; TaMin_C: -55°C; Polarized: N; SizeAreaWB_mm2: 4.68; Value1: Unknown; U/M: EA; Value: 0.22uF; TaMax_C: 125°C; SizeZ_mm: 1; SizeX_mm: 1.6; SizeY_mm: 0.8; SizeArea_mm2: 1.28; AEC Qualified: Y; AEC Category: Q200
C507-C510 C619 C624 C627 C628 = CMP-0085851-1: CAP, CERM, 22 pF, 50 V,+/- 5%, C0G/NP0, 0402; Manufacturer: Walsin; AEC Qualified: N; TaMax_C: 125°C; SizeX_mm: 1; Value: 22pF; SizeZ_mm: 0.6; AEC Category: Q200; TaMin_C: -55°C; SizeArea_mm2: 0.5; SizeAreaWB_mm2: 3; U/M: EA
C565 C590 C592 C600 C604 C615 = CMP-0007975-2: CAP, CERM, 2.2 uF, 25 V, +/- 10%, X7R, AEC-Q200 Grade 1, 0805; Manufacturer: TDK; TaMin_C: -55°C; Polarized: N; SizeAreaWB_mm2: 6.75; Value1: Unknown; U/M: EA; Value: 2.2uF; TaMax_C: 125°C; SizeZ_mm: 1.45; SizeX_mm: 2; SizeY_mm: 1.25; Cap_Case: 0805; SizeArea_mm2: 2.5; AEC Qualified: Y; AEC Grade: 1; AEC Category: Q200
C591 = CMP-0081062-1: CAP, CERM, 10 µF, 25 V,+/- 5%, X7R, AEC-Q200 Grade 1, 1206; Manufacturer: Kemet; TaMin_C: -55°C; Polarized: N; SizeAreaWB_mm2: 10.92; U/M: EA; Value: 10uF; TaMax_C: 125°C; SizeZ_mm: 1.8; SizeX_mm: 3.2; SizeY_mm: 1.6; SizeArea_mm2: 5.12; AEC Qualified: Y; AEC Grade: 1; AEC Category: Q200
C607 = CMP-0006318-2: CAP, CERM, 330 pF, 50 V, +/- 10%, X7R, AEC-Q200 Grade 1, 0402; Manufacturer: TDK; TaMin_C: -55°C; ESR_ohm: 6.5328; Polarized: N; SizeAreaWB_mm2: 3; Value1: 6.53276 ohm; U/M: EA; Value: 330pF; TaMax_C: 125°C; SizeZ_mm: 0.6; SizeX_mm: 1; SizeY_mm: 0.5; AEC Qualified: Y; IRMS_A: 212.649mA; AEC Category: Q200
C610 = CMP-0008776-2: CAP, CERM, 0.47 uF, 50 V, +/- 10%, X7R, AEC-Q200 Grade 1, 1206; Manufacturer: TDK; TaMin_C: -55°C; ESR_ohm: 9.426m; Polarized: N; SizeAreaWB_mm2: 10.92; Value1: 0.009426 ohm; U/M: EA; Value: 0.47uF; TaMax_C: 125°C; SizeZ_mm: 1.8; SizeX_mm: 3.2; SizeY_mm: 1.6; SizeArea_mm2: 5.12; AEC Qualified: Y; Cap_F: 470nF; IRMS_A: 2.37046A; AEC Grade: 1; AEC Category: Q200
C611 = CMP-0093287-1: Ceramic Capacitor for Automotive 10nF ±10% 50VDC X7R 0402 Paper T/R; Manufacturer: Murata; AEC Qualified: Yes; Tolerance_%: 0.1%; SizeZ_mm: 0.55mm; TempCo: 15%; AEC Grade: Grade 1
C612 = CMP-0093813-1: Cap Ceramic 10uF 6.3V X7R 10% Pad SMD 0805 +125°C Automotive T/R; Manufacturer: TDK Corporation; Value: 10µF; TempCo: 15%; AEC Qualified: Yes; AEC Grade: Grade 1; Tolerance_%: 0.1%; SizeZ_mm: 1.45mm
C613 C616 = CMP-0083705-1: CAP, CERM, 1 µF, 50 V,+/- 10%, X7R, AEC-Q200 Grade 1, 0805; Manufacturer: AVX; SizeAreaWB_mm2: 6.75; SizeArea_mm2: 2.5; AEC Qualified: Y; AEC Category: Q200; Value: 1uF; TaMax_C: 125°C; SizeZ_mm: 1.45; AEC Grade: 1; Polarized: N; TaMin_C: -55°C; SizeY_mm: 1.25; U/M: EA; SizeX_mm: 2; Cap_Case: 0805
D5 = CMP-0095722-1: Zener Diode 6.2 V 500 mW ±6.5% Surface Mount SOD-523; Manufacturer: onsemi; SizeZ_mm: 0.7mm; Vz_V: 6.2V; AEC Qualified: No; Vf_V: 6.6V; TJmax_C: 150°C; Vr_V: 4V; Zener Impedance: 10Ω; Power_W: 500mW; Max Reverse Leakage Current: 3uA
D6 = CMP-0028526-2: Diode, Schottky, 40 V, 0.5 A, SOD-123; Manufacturer: ON Semiconductor; Green_REACh: Passed; SizeY_mm: 1.7; Io_A: 500mA; SizeArea_mm2: 6.545; RJC_CperW: 118; Green_Lifecycle: Active; Vr_V: 40V; Vf_V: 510mV; TJmax_C: 150°C; AEC Category: Q101; SizeAreaWB_mm2: 13.095; Value1: 0.5A; SizeZ_mm: 1.35; SizeX_mm: 3.85; Value2: 0.51V; Value: 40V
FB1-FB3 FB500 = CMP-0086567-1: FERRITE BEAD 120 OHM 0402 1LN; Manufacturer: TDK; Imax_A: 0.4A; DCR_ohm: 0.18Ω; SizeZ_mm: 0.55mm; Symbol Name: SYM-MMZ1005Y121CTD25
J2 = CMP-0096269-1: Connector Header Surface Mount 9 position 0.039" (1.00mm); Manufacturer: Molex; Current_A: 1A; ContactFinish: Tin,Nickel; Row_Count: 1; AEC Qualified: No; Conn Orientation: Vertical; DUT-Pitch_mm: 1mm; Voltage_V: 100V; SizeZ_mm: 5.61mm; Conn Gender: Male
J3 = CMP-0086751-1: CONN HEADER SMD R/A 6POS 2MM; Manufacturer: Molex; Voltage_V: 125V; ContactFinish: Tin,Nickel; Row_Count: 1; Current_A: 3A
J7 J8 = CMP-0055291-1: Header(shrouded), 2mm, 3x1, Tin, R/A, SMT; Manufacturer: Molex; CNHeader: FALSE; Current_A: 3A; Shrouded: Y; Gender: Male; Voltage_V: 125V; Row_Count: 1; Pitch_mm: 2
J16 = CMP-0089821-1: Connector Header Through Hole 10 position 0.100" (2.54mm); Manufacturer: Molex; Voltage_V: 250V; Conn Gender: Male; SizeZ_mm: 9.47mm; Standoff Height: 0.38mm; Row_Count: 2; Conn Orientation: Vertical; AEC Qualified: No; ContactFinish: Gold,Nickel; Current_A: 2.5A
J500 = CMP-0089654-1: Easy-On FFC/FPC Connector 0.50mm Pitch, FD19 Series, Right-Angle, Bottom Contact, 1.90mm Height, 20 Circuits, Gold over Nickel Plating; Manufacturer: Molex; SizeZ_mm: 4.26mm; Is Female: yes; AEC Qualified: No; TaMin_C: -40°C; ContactFinish: Gold,Nickel; Voltage_V: 50V; Current_A: 500mA; DUT-Pitch_mm: 0.5mm; Conn Orientation: Right Angle; Conn Gender: Female; TaMax_C: +105°C
L6 L7 L500-L511 L525 L526 = CMP-0086567-1: FERRITE BEAD 120 OHM 0402 1LN; Manufacturer: TDK; PartNumber: MMZ1005Y121CTD25; Imax_A: 0.4A; DCR_ohm: 0.18Ω; SizeZ_mm: 0.55mm; Symbol Name: SYM-MMZ1005Y121CTD25
L8 = CMP-0062263-1: Inductor, Shielded Drum Core, Ferrite, 10 uH, 1.2 A, 0.124 ohm, SMD; Manufacturer: Sumida; Isat: 1.2A @ 35% inductance drop; Irms: 1.2A @ 30C rise; Green_Lifecycle: Not Set; SizeAreaWB_mm2: 64; DCR_ohm: 0.124; Green_REACh: Incomplete; Value: 10uH; Imax_A: 1.2A; SizeZ_mm: 2; SizeX_mm: 6; SizeArea_mm2: 36; Ind_H: 10µH; AEC Category: Q200
Q1 = CMP-0000642-2: MOSFET, N-CH, 30 V, 0.35 A, AEC-Q101, SOT-323; Alternate Manufacturer: None; Manufacturer: Nexperia; SizeZ_mm: 1.1; ChType: N; Value2: 0.52 nC; Value1: 1; VdsMax_V: 30V; SizeX_mm: 2.2; Vgs_V: 8V; AEC Qualified: Y; Value: 30V; Rdson45_ohm: 1.4; SizeArea_mm2: 4.84; AEC Category: Q101; IdsMax_A: 350mA; SizeAreaWB_mm2: 10.24; QgTyp_nC: 0.52
R6-R8 R26 R28-R30 R35 R41 R47 R52 R54 R61 R510-R512 R529 R559 R561 R569 R570 R574 R575 R579 R590 R591 = CMP-0026994-4: RES, 10 k, 5%, 0.1 W, AEC-Q200 Grade 0, 0402; Manufacturer: Panasonic; Power_W: 100mW; TempCo: 200 ppm/C; Value_Code: 10k0; U/M: EA; Value: 10k; EIA_Code: E24; SizeX_mm: 1; SizeY_mm: 0.5; SizeZ_mm: 0.6; Value2: 0.1W; AEC Qualified: Y; VDC_V: 50V; AEC Grade: 0; AEC Category: Q200
R10-R12 R19 R36 R62 R521-R523 R530 R532 R546 = CMP-0026696-1: RES, 33.0, 1%, 0.1 W, 0402; Manufacturer: Panasonic; Power_W: 100mW; TempCo: 100 ppm/C; Value_Code: 33R0; U/M: EA; Value: 33.0; Res_ohm: 33; SizeX_mm: 1; SizeY_mm: 0.5; SizeZ_mm: 0.6; Value2: 0.1W; VDC_V: 50V; AEC Category: Q200
R27 R50 R577 = CMP-0026071-3: RES, 1.00 k, 1%, 0.063 W, AEC-Q200 Grade 0, 0402; Manufacturer: Vishay-Dale; Power_W: 63mW; TempCo: 100 ppm/C; Value_Code: 1k00; Value: 1.00k; EIA_Code: E96; Res_ohm: 1k; SizeX_mm: 1; SizeY_mm: 0.5; SizeZ_mm: 0.6; Value2: 0.063W; AEC Qualified: Y; VDC_V: 50V; AEC Category: Q200; AEC Grade: 0
R55 = CMP-0081723-1: RES, 18.0 k, 1%, 0.1 W, AEC-Q200 Grade 0, 0402; Manufacturer: Panasonic; Power_W: 100mW; TempCo: 100 ppm/C; SizeAreaWB_mm2: 3; Value_Code: 18k0; Value: 18.0k; Res_ohm: 18k; SizeX_mm: 1; SizeY_mm: 0.5; SizeZ_mm: 0.6; Value2: 0.1W; AEC Qualified: Y; AEC Grade: 0; AEC Category: Q200
R57 = CMP-0025963-3: RES, 10.0, 1%, 0.063 W, AEC-Q200 Grade 0, 0402; Manufacturer: Vishay-Dale; Power_W: 63mW; TempCo: 100 ppm/C; Value_Code: 10R0; Value: 10.0; EIA_Code: E96; Res_ohm: 10; SizeX_mm: 1; SizeY_mm: 0.5; SizeZ_mm: 0.6; Value2: 0.063W; AEC Qualified: Y; VDC_V: 50V; AEC Category: Q200; AEC Grade: 0
R504 R506 R519 = CMP-0026517-2: RES, 6.81 k, 1%, 0.063 W, AEC-Q200 Grade 0, 0402; Manufacturer: Vishay-Dale; Power_W: 63mW; TempCo: 100 ppm/C; Value_Code: 6k81; Value: 6.81k; EIA_Code: E96; SizeX_mm: 1; SizeY_mm: 0.5; SizeZ_mm: 0.6; Value2: 0.063W; AEC Qualified: Y; VDC_V: 50V; AEC Category: Q200; AEC Grade: 0
R562 = CMP-0026996-2: RES, 20 k, 5%, 0.1 W, AEC-Q200 Grade 0, 0402; Manufacturer: Panasonic; Power_W: 100mW; TempCo: 200 ppm/C; Value_Code: 20k0; U/M: EA; Value: 20k; EIA_Code: E24; SizeX_mm: 1; SizeY_mm: 0.5; SizeZ_mm: 0.6; Value2: 0.1W; AEC Qualified: Y; VDC_V: 50V; AEC Grade: 0; AEC Category: Q200
R563 = CMP-0078244-2: RES, 30.0 k, 1%, 0.063 W, AEC-Q200 Grade 0, 0402; Manufacturer: Vishay-Dale; Power_W: 63mW; Green_Lifecycle: Active; TempCo: 100 ppm/C; Value_Code: 30k0; Green_REACh: Passed; Value: 30.0k; Res_ohm: 30k; SizeX_mm: 1; SizeY_mm: 0.5; SizeZ_mm: 0.6; Value2: 0.063W; AEC Qualified: Y; VDC_V: 50V; AEC Grade: 0; AEC Category: Q200
R565 = CMP-0026658-1: RES, 10.0 k, 1%, 0.1 W, 0402; Manufacturer: Panasonic; Power_W: 100mW; TempCo: 100 ppm/C; Value_Code: 10k0; U/M: EA; Value: 10.0k; EIA_Code: E96; Res_ohm: 10k; SizeX_mm: 1; SizeY_mm: 0.5; SizeZ_mm: 0.6; Value2: 0.1W; VDC_V: 50V; AEC Category: Q200
R566 = CMP-0026035-3: RES, 162, 1%, 0.063 W, AEC-Q200 Grade 0, 0402; Manufacturer: Vishay-Dale; Power_W: 63mW; TempCo: 100 ppm/C; Value_Code: 162R; Value: 162; EIA_Code: E96; SizeX_mm: 1; SizeY_mm: 0.5; SizeZ_mm: 0.6; Value2: 0.063W; AEC Qualified: Y; VDC_V: 50V; AEC Category: Q200; AEC Grade: 0
R573 = CMP-0026995-1: RES, 100 k, 5%, 0.1 W, AEC-Q200 Grade 0, 0402; Manufacturer: Panasonic; Power_W: 100mW; TempCo: 200 ppm/C; U/M: EA; Value: 100k; EIA_Code: E24; SizeX_mm: 1; SizeY_mm: 0.5; SizeZ_mm: 0.6; Value2: 0.1W; AEC Qualified: Y; VDC_V: 50V; AEC Grade: 0; AEC Category: Q200
R576 R578 = CMP-0026437-2: RES, 51.1 k, 1%, 0.063 W, AEC-Q200 Grade 0, 0402; Manufacturer: Vishay-Dale; Power_W: 63mW; TempCo: 100 ppm/C; Value_Code: 51k1; Value: 51.1k; EIA_Code: E96; SizeX_mm: 1; SizeY_mm: 0.5; SizeZ_mm: 0.6; Value2: 0.063W; AEC Qualified: Y; VDC_V: 50V; AEC Category: Q200; AEC Grade: 0
R585 = CMP-0026890-5: RES, 2.2 k, 5%, 0.063 W, AEC-Q200 Grade 0, 0402; Manufacturer: Vishay-Dale; Power_W: 63mW; TempCo: 200 ppm/C; Value_Code: 2k20; Value: 2.2k; EIA_Code: E24; SizeX_mm: 1; SizeY_mm: 0.5; SizeZ_mm: 0.6; Value2: 0.063W; AEC Qualified: Y; VDC_V: 50V; AEC Category: Q200; AEC Grade: 0
R586-R589 = CMP-0026544-2: RES, 75.0, 1%, 0.063 W, AEC-Q200 Grade 0, 0402; Manufacturer: Vishay-Dale; Power_W: 63mW; TempCo: 100 ppm/C; Value_Code: 75R0; Value: 75.0; EIA_Code: E96; Res_ohm: 75; SizeX_mm: 1; SizeY_mm: 0.5; SizeZ_mm: 0.6; Value2: 0.063W; AEC Qualified: Y; VDC_V: 50V; AEC Category: Q200; AEC Grade: 0
SW6 = CMP-0095672-1: Toggle Switch SPST Surface Mount, Right Angle; Manufacturer: C&K Components; SizeZ_mm: 5.46mm; VDC_V: 20V; AEC Qualified: No; Electromechanical Life: 40000Cycles; Coil Resistance_ohm: 50mΩ
TP6 TP13-TP15 = CMP-0078143-2: TEST POINT.  No entry in BOM.
U2 = CMP-0096130-1: Manufacturer: Texas Instruments; Standoff Height: 0.35mm; SizeZ_mm: 1.5mm
U6 = CMP-0750180-3: DLP® System Management and Illumination Controller for DLP553x-Q1 Chipset, PZP0100K (TQFP-100); Alternate Manufacturer: Texas Instruments; SizeX_mm: 16; Rating: Automotive; AEC Qualified: Y; SizeZ_mm: 1.2; SizeAreaWB_mm2: 324; AEC Category: Q200; CompType: IC; SizeArea_mm2: 256
U9 U10 = CMP-0050954-2: Automotive Catalog Low-Voltage Single FET Bus Switch, DBV0005A (SOT-23-5); Generic Part Number: SN74CBTLV1G125-Q1; Manufacturer: Texas Instruments; Bits(#): 1; Schmitt Trigger: No; VCC(Min)(V): 2.3; Input Type: LV-CMOS; Switch Configuration: SPST; Output Type: CMOS; F @ Nom Voltage(Max)(Mhz): 200; VCC(Max)(V): 3.6; tpd @ Nom Voltage(Max)(ns): 0.25; Logic: True; ICC @ Nom Voltage(Max)(mA): 0.01; Voltage(Nom)(V): 3.3; AEC Category: Q200; AEC Qualified: Y; CompType: IC; SizeAreaWB_mm2: 14.82; SizeArea_mm2: 8.12; SizeX_mm: 2.8; SizeY_mm: 2.9; SizeZ_mm: 1.45
U13 = CMP-0051661-3: Automotive Catalog Single Inverter, DCK0005A, LARGE T&R; Manufacturer: Texas Instruments; Generic Part Number: SN74LVC1G04-Q1; Logic: Inverting; Input Type: CMOS/TTL; 3-State Output: No; Voltage(Nom)(V): 1.8,2.5,3.3,5; tpd @ Nom Voltage(Max)(ns): 7.5,5.2,4.2,3.7; Sub-Family: Inverting Buffer/Driver; Bits(#): 1; VCC(Min)(V): 1.65; F @ Nom Voltage(Max)(Mhz): 150; ICC @ Nom Voltage(Max)(mA): 0.01; Technology Family: LVC; Output Drive (IOL/IOH)(Max)(mA): 32/-32; Output Type: CMOS; VCC(Max)(V): 5.5; AEC Category: Q200; AEC Qualified: Y; CompType: IC; SizeAreaWB_mm2: 9.3; SizeArea_mm2: 4.2; SizeX_mm: 2.1; SizeY_mm: 2.0; SizeZ_mm: 1.1
U14 = CMP-0054515-1: Automotive Catalog Quadruple 2-Input Positive-AND Gate, PW0014A, LARGE T&R; Manufacturer: Texas Instruments; Generic Part Number: SN74LVC08A-Q1; Voltage(Nom)(V): 2.7,3.3; VCC(Max)(V): 3.6; Technology Family: LVC; VCC(Min)(V): 2; Output Type: TTL; Output Drive (IOL/IOH)(Max)(mA): -24/24; F @ Nom Voltage(Max)(Mhz): 70; ICC @ Nom Voltage(Max)(mA): 0.01; Bits(#): 4; tpd @ Nom Voltage(Max)(ns): 4.8,4.1; Schmitt Trigger: Yes
U513 = CMP-0073599-3: Automotive 4-Channel ESD Protection Solution for SuperSpeed (up to 5 Gbps) Interface, DQA0010A (USON-10); Manufacturer: Texas Instruments; SizeZ_mm: 0.55; SizeX_mm: 1.0; SizeY_mm: 2.5; CompType: IC; SizeAreaWB_mm2: 7.0; AEC Category: Q200; AEC Qualified: Y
